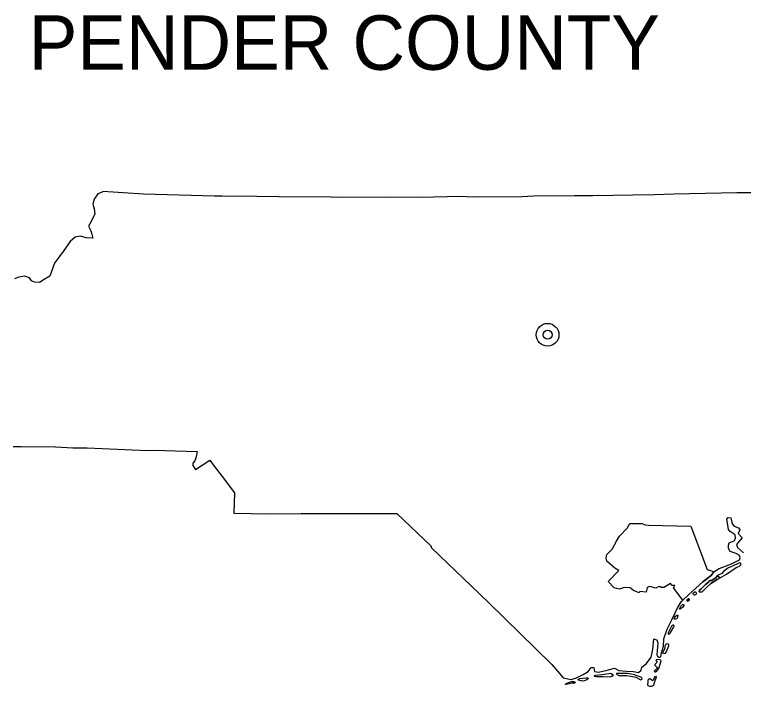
# Model space of a CAD drawing. Extents: x -2362 to 1945, y 0 to 1100.
# Drawn here: x 1588.25 to 1636.45, y 973 to 1017.46 of the extents above; entities that cross this region are included whole.
import ezdxf

# ---------------------------------------------------------------- set-up
doc = ezdxf.new("R2010")
doc.units = 0
doc.layers.add('Exist Utilities Gas Test Hole SUE LOS A CELL', color=7, linetype='Continuous')
doc.layers.add('Sheet PE Seal CELL', color=7, linetype='Continuous')

msp = doc.modelspace()

# ---------------------------------------------------------------- linework, layer by layer
at = {"layer": 'Exist Utilities Gas Test Hole SUE LOS A CELL'}
for points in [[(1631.909, 979.673), (1631.735, 979.69), (1631.618, 979.805), (1631.178, 979.557), (1631.014, 979.558), (1630.928, 979.613), (1630.8, 979.581), (1630.649, 979.499), (1630.258, 979.606), (1630.083, 979.542), (1630.014, 979.23), (1629.599, 979.274), (1629.543, 979.189), (1629.177, 979.359), (1628.961, 979.53), (1628.554, 979.545), (1628.263, 979.446), (1628.064, 979.48), (1627.894, 979.522), (1627.502, 979.938), (1628.202, 980.67), (1627.955, 980.82), (1627.422, 981.301), (1627.363, 981.513), (1627.412, 981.721), (1627.762, 982.081), (1628.046, 982.615), (1628.254, 982.945), (1628.758, 983.482), (1628.946, 983.775), (1629.402, 983.792), (1629.758, 983.786), (1629.946, 983.686), (1630.177, 983.674), (1632.98, 983.611), (1634.041, 980.734), (1634.264, 980.682), (1634.491, 980.574), (1634.324, 980.333), (1633.758, 979.919), (1632.842, 979.08), (1632.45, 978.717), (1631.828, 979.525)], [(1634.702, 980.071), (1634.284, 979.814), (1634.023, 979.561), (1633.714, 979.272), (1633.568, 979.235), (1633.532, 979.285), (1633.547, 979.361), (1633.624, 979.445), (1633.945, 979.752), (1634.147, 979.903), (1634.17, 979.936), (1634.242, 980.01), (1634.358, 980.021), (1634.645, 980.219), (1634.729, 980.344), (1634.911, 980.192)], [(1633.123, 979.177), (1633.244, 979.256), (1633.283, 979.262), (1633.333, 979.211), (1633.341, 979.178), (1633.326, 979.13), (1633.29, 979.086), (1633.254, 979.06), (1633.224, 979.05), (1633.19, 979.046), (1633.152, 979.081), (1633.115, 979.13)], [(1632.863, 978.708), (1632.76, 978.653), (1632.722, 978.718), (1632.776, 978.778)]]:
    msp.add_lwpolyline(points, close=True, dxfattribs=at)
for radius in [0.752, 0.3]:
    msp.add_circle((1623.5, 996.27), radius, dxfattribs=at)
at = {"layer": 'Sheet PE Seal CELL'}
for points in [[(1637.767, 1005.667), (1636.007, 1005.661), (1631.854, 1005.569), (1630.568, 1005.527), (1629.128, 1005.496), (1626.496, 1005.468), (1625.258, 1005.452), (1622.589, 1005.446), (1621.795, 1005.395), (1618.594, 1005.382), (1617.714, 1005.41), (1615.069, 1005.352), (1612.887, 1005.382), (1609.813, 1005.346), (1609.189, 1005.384), (1605.718, 1005.394), (1604.28, 1005.421), (1601.974, 1005.443), (1601.468, 1005.431), (1596.787, 1005.562), (1594.085, 1005.742), (1594.052, 1005.705), (1593.757, 1005.592), (1593.515, 1005.252), (1593.428, 1004.92), (1593.51, 1004.593), (1593.564, 1004.27), (1593.334, 1003.805), (1593.146, 1003.446), (1593.286, 1003.139), (1593.369, 1002.923), (1593.43, 1002.654), (1593.015, 1002.681), (1592.598, 1002.79), (1592.269, 1002.723), (1591.926, 1002.451), (1591.358, 1001.634), (1591.31, 1001.585), (1590.9, 1001.008), (1590.578, 1000.146), (1590.201, 999.921), (1589.898, 999.727), (1589.569, 999.755), (1589.372, 999.848), (1589.231, 1000.043), (1588.926, 1000.15), (1588.543, 1000.089), (1588.249, 999.962)], [(1588.161, 988.88), (1588.681, 988.869), (1590.969, 988.85), (1592.101, 988.799), (1593.046, 988.785), (1597.03, 988.609), (1597.432, 988.636), (1600.317, 988.553), (1600.253, 988.197), (1600.175, 987.937), (1600.041, 987.766), (1600.047, 987.617), (1600.215, 987.35), (1601.168, 987.975), (1601.442, 987.586), (1601.973, 986.889), (1602.789, 985.802), (1602.745, 984.458), (1605.092, 984.422), (1607.203, 984.454), (1611.225, 984.44), (1613.377, 984.453), (1613.54, 984.442), (1615.797, 982.272), (1615.811, 982.189), (1619.579, 978.567), (1623.778, 974.451), (1624.539, 973.575)], [(1624.539, 973.575), (1625.063, 973.462), (1625.419, 973.564), (1625.85, 973.787), (1626.182, 973.987), (1626.39, 974.247), (1626.566, 974.245), (1626.605, 973.997), (1626.866, 973.94), (1627.445, 974.071), (1627.929, 974.204), (1628.202, 974.051), (1628.71, 974.005), (1629.182, 973.992), (1629.51, 973.923), (1629.686, 974.081), (1629.721, 974.276), (1630.048, 974.516), (1630.338, 974.936), (1630.454, 975.44), (1630.523, 976.141), (1630.562, 976.134), (1630.732, 976.091), (1630.79, 975.88), (1630.721, 975.099), (1630.763, 974.997), (1630.852, 974.934), (1630.94, 974.935), (1630.979, 974.991), (1631.03, 975.234), (1631.161, 975.668), (1631.191, 976.147), (1631.398, 976.784), (1631.734, 977.453), (1632.121, 978.248), (1632.363, 978.611), (1632.45, 978.717), (1632.842, 979.08), (1633.758, 979.919), (1634.324, 980.333), (1634.491, 980.574), (1634.848, 980.809), (1635.669, 981.11), (1636.182, 981.371), (1636.227, 981.539), (1636.158, 981.686), (1635.973, 981.8), (1635.573, 981.938), (1635.471, 982.132), (1635.454, 982.338), (1635.498, 982.506), (1635.837, 982.636), (1635.934, 982.795), (1635.895, 983.032), (1635.701, 983.175), (1635.58, 983.264), (1635.453, 983.395), (1635.341, 984.065), (1635.445, 984.182), (1635.605, 984.154), (1635.698, 983.758), (1635.833, 983.598), (1636.13, 983.492), (1636.204, 983.37), (1636.105, 983.13), (1636.366, 982.827), (1636.088, 982.51), (1635.985, 982.393), (1636.058, 982.191), (1636.459, 981.836)], [(1633.945, 979.752), (1633.624, 979.445), (1633.547, 979.361), (1633.532, 979.285), (1633.568, 979.235), (1633.714, 979.272), (1634.023, 979.561), (1634.284, 979.814), (1634.702, 980.071), (1635.33, 980.434), (1635.972, 980.874), (1636.198, 980.965), (1636.255, 981.021), (1636.309, 981.14), (1636.188, 981.186), (1636.02, 981.096), (1635.604, 980.919), (1635.416, 980.836), (1635.156, 980.636), (1635.017, 980.483), (1634.729, 980.344), (1634.645, 980.219), (1634.358, 980.021), (1634.242, 980.01), (1634.17, 979.936), (1634.147, 979.903), (1633.959, 979.761)], [(1632.776, 978.778), (1632.722, 978.718), (1632.716, 978.685), (1632.731, 978.659), (1632.76, 978.653), (1632.807, 978.666), (1632.863, 978.708), (1632.884, 978.734), (1632.877, 978.758), (1632.83, 978.8), (1632.814, 978.806), (1632.792, 978.797), (1632.78, 978.783)], [(1633.123, 979.177), (1633.244, 979.256), (1633.283, 979.262), (1633.306, 979.244), (1633.333, 979.211), (1633.341, 979.178), (1633.326, 979.13), (1633.29, 979.086), (1633.254, 979.06), (1633.224, 979.05), (1633.19, 979.046), (1633.152, 979.081), (1633.115, 979.13), (1633.109, 979.157), (1633.123, 979.177)], [(1632.238, 978.183), (1632.312, 978.307), (1632.39, 978.391), (1632.437, 978.426), (1632.473, 978.429), (1632.503, 978.402), (1632.521, 978.364), (1632.482, 978.32), (1632.415, 978.23), (1632.356, 978.171), (1632.267, 978.123), (1632.241, 978.122), (1632.223, 978.135), (1632.215, 978.15), (1632.238, 978.183)], [(1631.873, 977.484), (1631.914, 977.575), (1631.966, 977.65), (1632.015, 977.689), (1632.074, 977.72), (1632.108, 977.711), (1632.121, 977.68), (1632.099, 977.61), (1632.061, 977.525), (1632.02, 977.485), (1631.965, 977.449), (1631.893, 977.456), (1631.875, 977.464), (1631.872, 977.491)], [(1631.478, 976.538), (1631.469, 976.451), (1631.484, 976.444), (1631.519, 976.449), (1631.569, 976.477), (1631.599, 976.516), (1631.856, 976.947), (1631.865, 977.004), (1631.855, 977.034), (1631.817, 977.06), (1631.78, 977.06), (1631.726, 977.029), (1631.694, 976.989), (1631.495, 976.599), (1631.477, 976.539)], [(1631.269, 975.546), (1631.275, 975.669), (1631.284, 975.76), (1631.326, 975.806), (1631.386, 975.832), (1631.445, 975.815), (1631.503, 975.77), (1631.502, 975.657), (1631.348, 975.292), (1631.261, 975.188), (1631.183, 975.149), (1631.135, 975.171), (1631.129, 975.231), (1631.191, 975.363), (1631.271, 975.553)], [(1630.734, 974.615), (1630.684, 974.532), (1630.601, 974.474), (1630.589, 974.449), (1630.594, 974.416), (1630.683, 974.323), (1630.73, 974.284), (1630.749, 974.269), (1630.748, 974.219), (1630.57, 974.033), (1630.555, 974.006), (1630.608, 973.964), (1630.644, 973.976), (1630.727, 974.027), (1630.862, 974.187), (1631.009, 974.693)], [(1631.009, 974.693), (1630.935, 974.765), (1630.761, 974.79), (1630.703, 974.755), (1630.664, 974.721), (1630.674, 974.686), (1630.734, 974.615)], [(1625.62, 973.518), (1626.051, 973.574), (1626.136, 973.573), (1626.177, 973.558), (1626.163, 973.492), (1626.103, 973.444), (1625.92, 973.371), (1625.779, 973.351), (1625.556, 973.407), (1625.498, 973.436), (1625.535, 973.485), (1625.63, 973.526)], [(1626.668, 973.754), (1627.088, 973.787), (1627.553, 973.866), (1627.669, 973.873), (1627.766, 973.821), (1627.819, 973.756), (1627.807, 973.713), (1627.697, 973.633), (1627.614, 973.61), (1627.163, 973.634), (1626.838, 973.643), (1626.704, 973.644), (1626.631, 973.666), (1626.603, 973.69), (1626.603, 973.708), (1626.607, 973.723), (1626.666, 973.749)], [(1628.049, 973.824), (1628.212, 973.72), (1628.383, 973.727), (1628.706, 973.716), (1628.998, 973.684), (1629.327, 973.613), (1629.57, 973.485), (1629.672, 973.441), (1629.762, 973.482), (1629.741, 973.568), (1629.67, 973.617), (1629.179, 973.782), (1628.785, 973.858), (1628.139, 973.865), (1628.049, 973.854), (1628.054, 973.824)], [(1630.256, 973.521), (1630.418, 973.407), (1630.459, 973.393), (1630.518, 973.464), (1630.597, 973.657), (1630.642, 973.677), (1630.678, 973.617), (1630.527, 973.177), (1630.493, 973.07), (1630.363, 973.008), (1630.252, 973.002), (1630.151, 973.041), (1630.119, 973.141), (1630.158, 973.263), (1630.146, 973.434), (1630.16, 973.47), (1630.245, 973.526), (1630.271, 973.521)], [(1624.681, 973.159), (1624.769, 973.218), (1624.946, 973.291), (1625.066, 973.321), (1625.143, 973.327), (1625.209, 973.319), (1625.283, 973.299), (1625.318, 973.284), (1625.327, 973.265), (1625.32, 973.251), (1625.235, 973.205), (1625.215, 973.212), (1625.197, 973.227), (1625.118, 973.211), (1624.956, 973.18), (1624.818, 973.143), (1624.737, 973.122), (1624.707, 973.119), (1624.689, 973.137), (1624.681, 973.159)]]:
    msp.add_lwpolyline(points, dxfattribs=at)

# ---------------------------------------------------------------- texts
msp.add_text('PENDER COUNTY', height=3.6, rotation=0, dxfattribs=at).set_placement((1589.196, 1013.803))

doc.saveas('drawing.dxf')
